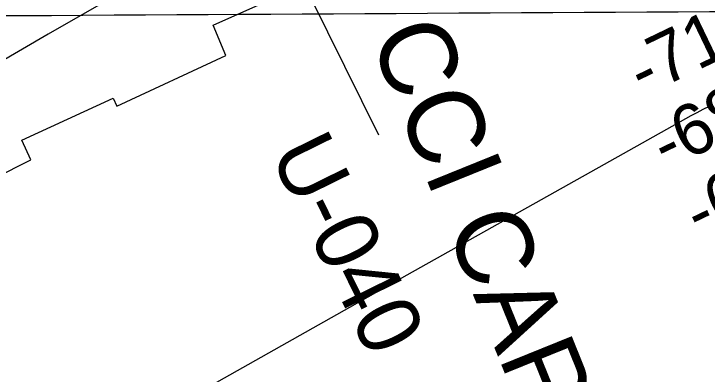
# Model space of a CAD drawing. Extents: x 3477039 to 3515015, y 546746 to 572297.
# Drawn here: x 3490710 to 3491621, y 563812 to 564285 of the extents above; entities that cross this region are included whole.
import ezdxf

# ---------------------------------------------------------------- set-up
doc = ezdxf.new("R2010")
doc.units = 0
for name, color, linetype in [('V-CHAN-NAID', 7, 'Continuous'), ('V-GRID-MAJR', 7, 'Continuous'), ('V-RIVR-RANG', 7, 'Continuous'), ('V-RIVR-RANG-IDEN', 7, 'Continuous'), ('V-RRAP-RVMT', 7, 'Continuous'), ('V-TOPO-MINR', 7, 'Continuous')]:
    doc.layers.add(name, color=color, linetype=linetype)

msp = doc.modelspace()

# ---------------------------------------------------------------- linework, layer by layer
at = {"layer": 'V-GRID-MAJR'}
msp.add_spline([(3481202.02, 564229.25), (3486474.82, 564258.78), (3491747.62, 564289.07), (3497020.42, 564320.13), (3502293.21, 564351.96), (3507565.99, 564384.55), (3512838.77, 564417.92)], degree=3, dxfattribs=at)
at = {"layer": 'V-RIVR-RANG'}
msp.add_line((3490709.61, 565094.48), (3491188.7, 564126.56), dxfattribs=at)
at = {"layer": 'V-RRAP-RVMT'}
msp.add_lwpolyline([(3490067.1, 563798.55), (3490201.79, 563876.16), (3490200.14, 563879.89), (3490310.75, 563937.66), (3490328.02, 563905.03), (3490469.46, 563979.61), (3490466.6, 563986.15), (3490577.53, 564041.81), (3490589.14, 564021.73), (3490731.95, 564093.76), (3490719.89, 564119.63), (3490840.06, 564174.36), (3490845.02, 564164.11), (3490988.06, 564230.44), (3490971.36, 564270.27), (3491099.5, 564327.58), (3491105.15, 564314.66), (3491244.11, 564374.86), (3491242.77, 564378.55), (3491366.04, 564432.66), (3491368.09, 564428.27), (3491500.21, 564489.5), (3491504.52, 564480.45), (3491649.23, 564546.95)], dxfattribs=at)
at = {"layer": 'V-TOPO-MINR'}
for points in [[(3491989.22, 564864.03), (3491417.38, 564620.61), (3491408.48, 564616.69), (3491399.66, 564612.6), (3491390.94, 564608.29), (3491382.29, 564603.83), (3491183.08, 564497.63), (3491075.23, 564439.34), (3490967.83, 564380.24), (3490861.12, 564319.91), (3490754.86, 564258.76), (3490281.74, 563982.91), (3490252.73, 563966.24), (3490223.6, 563949.81), (3490194.26, 563933.74), (3490164.79, 563917.91), (3489547.44, 563591.23)], [(3489582.14, 563044.99), (3489634.21, 563072.12), (3489686.22, 563099.36), (3489738.13, 563126.77), (3489789.99, 563154.3), (3490406.93, 563483.11), (3490435.28, 563498.34), (3490463.55, 563513.7), (3490491.72, 563529.25), (3490519.82, 563544.93), (3491226.55, 563942.43), (3491291.34, 563978.84), (3491356.15, 564015.22), (3491420.99, 564051.55), (3491485.84, 564087.85), (3491599.93, 564151.65), (3491607.81, 564155.91), (3491615.77, 564160.01), (3491623.84, 564163.89)]]:
    msp.add_lwpolyline(points, dxfattribs=at)

# ---------------------------------------------------------------- texts
at = {"layer": 'V-CHAN-NAID'}
msp.add_text('CCI CARBON (145.6) (3)', height=100, rotation=292.01128, dxfattribs=at).set_placement((3491176.21, 564254.89))
at = {"layer": 'V-RIVR-RANG'}
for s, p in [('-71', (3491536.23, 564176.16)), ('-68', (3491566.72, 564079.87)), ('-66', (3491610.28, 563989.85))]:
    msp.add_text(s, height=67, rotation=25.66525, dxfattribs=at).set_placement(p)
at = {"layer": 'V-RIVR-RANG-IDEN'}
msp.add_text('U-040', height=83, rotation=296.19233, dxfattribs=at).set_placement((3491044.97, 564101.82))

doc.saveas('drawing.dxf')
